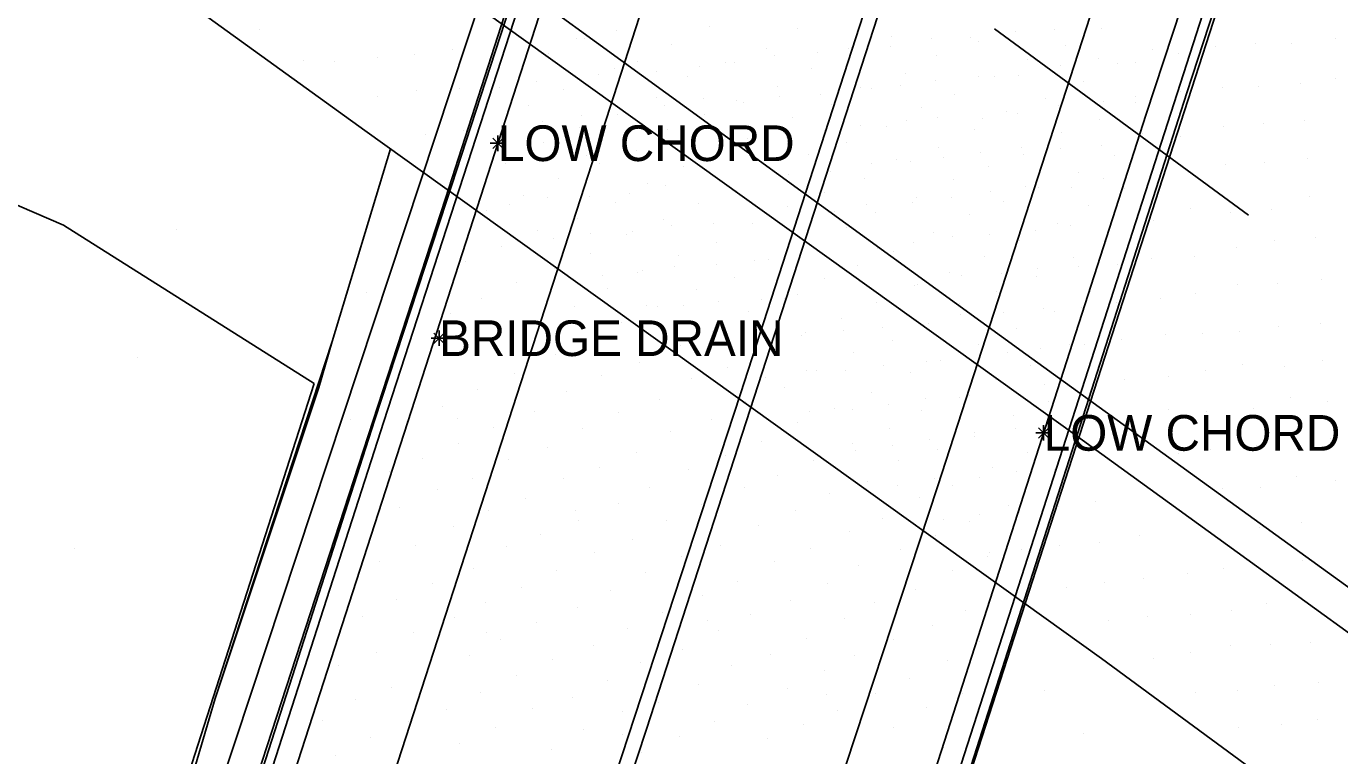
# Model space of a CAD drawing. Extents: x 0 to 1739264, y 0 to 465304.
# Drawn here: x 1738782.8 to 1738849.1, y 464563.4 to 464600.2 of the extents above; entities that cross this region are included whole.
import ezdxf

# ---------------------------------------------------------------- set-up
doc = ezdxf.new("R2010")
doc.units = 0
for name, color, linetype in [('Default', 7, 'Continuous'), ('S_Ground_SpotElevation', 7, 'Continuous'), ('S_Misc_MiscItems', 7, 'Continuous'), ('S_Terrain_Boundary', 7, 'Continuous'), ('S_Terrain_Holes', 7, 'Continuous'), ('S_Terrain_Imported_Contours', 7, 'Continuous'), ('S_Terrain_Low_Points', 7, 'Continuous'), ('S_Terrain_Major_Contours_Label', 7, 'Continuous'), ('S_Terrain_Minor_Contours', 7, 'Continuous'), ('S_Terrain_Spots', 7, 'Continuous'), ('S_Terrain_Triangles', 7, 'Continuous'), ('S_Terrain_Voids', 7, 'Continuous'), ('S_Text', 7, 'Continuous')]:
    doc.layers.add(name, color=color, linetype=linetype)

# ---------------------------------------------------------------- blocks, each defined once
blk = doc.blocks.new('POINT_DISPLAY')
at = {"layer": 'Default'}
blk.add_line((0, 0), (0, 0), dxfattribs=at)

msp = doc.modelspace()

# ---------------------------------------------------------------- linework, layer by layer
at = {"layer": 'S_Misc_MiscItems'}
for p, q in [((1738806.898081, 464594.035019), (1738806.373919, 464594.559181)), ((1738806.898081, 464594.559181), (1738806.373919, 464594.035019)), ((1738806.636, 464594.690025), (1738806.636, 464593.904175)), ((1738807.028925, 464594.2971), (1738806.243075, 464594.2971)), ((1738803.928081, 464584.194319), (1738803.403919, 464584.718481)), ((1738803.928081, 464584.718481), (1738803.403919, 464584.194319)), ((1738803.666, 464584.849325), (1738803.666, 464584.063475)), ((1738804.058925, 464584.4564), (1738803.273075, 464584.4564)), ((1738834.447081, 464579.415419), (1738833.922919, 464579.939581)), ((1738834.447081, 464579.939581), (1738833.922919, 464579.415419)), ((1738834.185, 464580.070425), (1738834.185, 464579.284575)), ((1738834.577925, 464579.6775), (1738833.792075, 464579.6775))]:
    msp.add_line(p, q, dxfattribs=at)
at = {"layer": 'S_Terrain_Boundary'}
msp.add_lwpolyline([(1739175.454702, 464332.756416), (1739132.535909, 464364.041084), (1739089.202901, 464395.459113), (1739026.971303, 464440.302894), (1738965.452398, 464485.286597), (1738903.800699, 464530.134498), (1738862.3172, 464560.363013), (1738835.176198, 464580.019813), (1738796.240903, 464607.926002), (1738740.499395, 464648.201392), (1738691.282796, 464684.125205), (1738636.830999, 464723.670798), (1738593.459401, 464755.033195), (1738538.967885, 464794.669395), (1738484.361104, 464834.444198), (1738424.006185, 464878.237201)], dxfattribs=at)
at = {"layer": 'S_Terrain_Holes'}
msp.add_lwpolyline([(1739170.588308, 464325.500373), (1739152.552907, 464338.483527), (1739114.826696, 464366.236518), (1739080.0463, 464391.153388), (1739045.200704, 464417.071418), (1738978.615499, 464465.012885), (1738944.577802, 464489.97779), (1738904.0454, 464519.108802), (1738859.5087, 464551.815192), (1738837.105501, 464568.288306), (1738799.9269, 464594.941993), (1738767.332898, 464618.452308), (1738734.240804, 464642.564887), (1738701.246496, 464666.335303), (1738672.330098, 464687.406394), (1738626.181707, 464720.896705), (1738547.219503, 464778.355994), (1738497.724386, 464814.494201), (1738418.864705, 464871.408801)], dxfattribs=at)
at = {"layer": 'S_Terrain_Imported_Contours'}
msp.add_line((1738831.709901, 464600.078407), (1738844.528501, 464590.671485), dxfattribs=at)
for points in [[(1738424.884389, 464880.1622), (1738459.014211, 464855.316497), (1738501.687795, 464824.364303), (1738553.815297, 464786.542793), (1738615.385396, 464741.680198), (1738657.550603, 464711.303596), (1738696.071996, 464683.218208), (1738726.299306, 464661.147315), (1738787.670598, 464616.772407), (1738833.2893, 464583.65409), (1738892.3085, 464540.999702), (1738935.664502, 464509.412086), (1738985.514898, 464473.308387), (1739035.486196, 464436.916999), (1739078.275106, 464405.912605), (1739127.816915, 464370.067023), (1739176.551595, 464334.499702)], [(1738861.917132, 464749.554455), (1738852.728099, 464720.865302), (1738834.137899, 464663.640296), (1738810.806299, 464591.494392), (1738798.57878, 464553.775144)], [(1738807.560265, 464547.101191), (1738818.883699, 464581.650611), (1738840.7733, 464649.227912), (1738859.7717, 464707.561698), (1738871.099421, 464743.042961)], [(1738871.2811, 464741.761298), (1738862.9528, 464715.336097), (1738835.861902, 464631.717414), (1738814.1443, 464564.731208), (1738808.177672, 464546.642409)], [(1738816.833754, 464540.526168), (1738828.844899, 464576.996803), (1738841.383399, 464615.664314), (1738851.1298, 464645.487891), (1738867.0642, 464694.79), (1738880.224773, 464736.284008)]]:
    msp.add_lwpolyline(points, dxfattribs=at)
at = {"layer": 'S_Terrain_Low_Points'}
for points in [[(1738792.605864, 464561.753915), (1738808.947702, 464611.187598), (1738829.7665, 464675.843208), (1738844.662601, 464721.815192), (1738854.169417, 464751.567291)], [(1738856.4555, 464747.969505), (1738838.244399, 464692.009101), (1738826.647699, 464655.847602), (1738824.734399, 464649.915199), (1738812.578801, 464612.657905), (1738795.808896, 464560.843085)], [(1738851.7415, 464633.401588), (1738839.363599, 464595.771888), (1738822.210698, 464542.4672)], [(1738801.216888, 464594.017189), (1738798.264997, 464584.296485), (1738792.365444, 464566.267756), (1738791.152246, 464562.167502), (1738792.484382, 464561.299763)]]:
    msp.add_lwpolyline(points, dxfattribs=at)
at = {"layer": 'S_Terrain_Major_Contours_Label'}
for points in [[(1738793.029831, 464557.898451), (1738803.9838, 464591.509406), (1738812.589898, 464618.183295), (1738822.305799, 464648.240607), (1738833.2133, 464681.803199), (1738842.84, 464711.786903), (1738850.196, 464734.470405), (1738856.340829, 464753.508813)], [(1738885.395159, 464732.452095), (1738884.2943, 464729.028999), (1738875.3401, 464701.327995), (1738857.6966, 464646.653999), (1738844.752799, 464606.659614), (1738829.9694, 464560.926002), (1738822.141572, 464536.77828)]]:
    msp.add_lwpolyline(points, dxfattribs=at)
at = {"layer": 'S_Terrain_Minor_Contours'}
for points in [[(1738794.472612, 464560.340831), (1738800.87399, 464580.245445), (1738812.939284, 464617.414493)], [(1738822.502035, 464539.871865), (1738828.574695, 464558.460113), (1738842.68621, 464602.312192), (1738844.286302, 464607.201361)]]:
    msp.add_lwpolyline(points, dxfattribs=at)
at = {"layer": 'S_Terrain_Spots'}
msp.add_lwpolyline([(1738801.216888, 464594.017189), (1738798.264997, 464584.296485), (1738797.595653, 464581.962025), (1738792.365444, 464566.267756), (1738791.152246, 464562.167502)], dxfattribs=at)
at = {"layer": 'S_Terrain_Triangles'}
for points in [[(1738793.143077, 464557.8143), (1738794.925598, 464563.221652), (1738800.413936, 464580.303997), (1738804.057897, 464591.416999), (1738810.426301, 464610.960395), (1738818.2273, 464635.285011), (1738828.789701, 464667.726112), (1738838.3903, 464697.576408), (1738845.034101, 464718.107597), (1738853.3717, 464743.659003), (1738856.448989, 464753.432112)], [(1738885.339743, 464732.493165), (1738884.4636, 464729.823402), (1738878.6737, 464712.005698), (1738871.4064, 464689.647605), (1738862.8085, 464662.946113), (1738850.8758, 464625.801398), (1738841.409499, 464596.833595), (1738830.533101, 464562.882606), (1738822.877599, 464539.516792), (1738822.019587, 464536.864414)]]:
    msp.add_lwpolyline(points, dxfattribs=at)
at = {"layer": 'S_Terrain_Voids'}
msp.add_line((1738797.357, 464582.164802), (1738791.034597, 464562.502906), dxfattribs=at)
msp.add_lwpolyline([(1738657.937398, 464655.498206), (1738707.784398, 464616.152808), (1738731.372304, 464597.946906), (1738739.378301, 464595.018104), (1738746.050298, 464593.852699), (1738752.398702, 464595.526496), (1738762.3794, 464598.047309), (1738774.3215, 464594.638404), (1738784.707403, 464590.162605), (1738797.357, 464582.164802)], dxfattribs=at)

# ---------------------------------------------------------------- block references
at = {"layer": 'S_Ground_SpotElevation'}
for p in [(1738794.62611, 464600.041525), (1738812.635814, 464599.998922), (1738817.322993, 464600.199699), (1738821.761897, 464600.074516), (1738832.786998, 464599.9186), (1738834.735302, 464600.02532), (1738837.115001, 464600.077324), (1738806.440105, 464599.136526), (1738810.58131, 464599.601827), (1738810.998393, 464599.600273), (1738815.380595, 464599.280205), (1738820.198695, 464599.074089), (1738824.336192, 464599.061516), (1738824.484997, 464599.108816), (1738826.475902, 464599.183004), (1738826.493693, 464599.671989), (1738828.547405, 464599.584219), (1738830.494793, 464599.64562), (1738830.9136, 464599.447197), (1738835.266902, 464599.214226), (1738842.864299, 464599.174703), (1738844.886608, 464599.310812), (1738846.697796, 464599.342703), (1738848.933086, 464599.566305), (1738796.803905, 464598.474508), (1738798.397014, 464598.413625), (1738800.560894, 464598.612722), (1738802.420696, 464598.768118), (1738804.348095, 464599.043111), (1738809.175395, 464598.821403), (1738813.692195, 464598.410515), (1738820.601391, 464598.713705), (1738822.745891, 464598.865621), (1738828.783198, 464598.733391), (1738833.389293, 464598.545219), (1738836.936504, 464598.5548), (1738839.676799, 464599.014274), (1738840.975689, 464598.83251), (1738811.732799, 464597.782524), (1738812.529888, 464598.048116), (1738814.664196, 464597.928518), (1738816.797893, 464598.162222), (1738818.115703, 464598.362602), (1738818.586712, 464598.348806), (1738822.4743, 464598.056023), (1738827.226298, 464597.82), (1738835.035503, 464598.206411), (1738837.932704, 464598.306328), (1738838.822704, 464598.353506), (1738806.694408, 464597.122823), (1738808.585094, 464597.398611), (1738816.194804, 464597.654289), (1738820.760493, 464597.137993), (1738824.945812, 464597.127218), (1738825.482494, 464597.069816), (1738826.9622, 464597.220113), (1738828.733989, 464597.48171), (1738830.895611, 464597.642721), (1738831.711696, 464597.652519), (1738832.892009, 464597.728323), (1738836.188899, 464597.413017), (1738843.191997, 464597.087301), (1738845.041485, 464597.135915), (1738847.146892, 464597.300314), (1738848.895885, 464597.584402), (1738800.567211, 464596.648519), (1738802.536297, 464596.948812), (1738804.700512, 464597.068014), (1738809.932994, 464596.998405), (1738814.644298, 464596.594108), (1738817.011913, 464596.544424), (1738818.670299, 464596.461202), (1738820.860698, 464596.638021), (1738822.900707, 464596.735403), (1738829.6804, 464596.738029), (1738834.277995, 464596.557487), (1738837.181987, 464596.424612), (1738838.829998, 464596.662405), (1738841.081585, 464596.906118), (1738808.175105, 464596.176872), (1738815.045299, 464596.190725), (1738817.061595, 464595.751884), (1738819.043193, 464596.329704), (1738823.459407, 464596.246025), (1738828.0312, 464596.11663), (1738832.294398, 464595.922172), (1738832.882915, 464595.798513), (1738834.956615, 464596.208212), (1738838.840495, 464596.348076), (1738807.049297, 464595.156026), (1738808.897289, 464595.407217), (1738810.851207, 464595.713216), (1738812.681407, 464595.732719), (1738821.509196, 464595.618828), (1738824.933788, 464595.202505), (1738826.245296, 464595.165581), (1738827.274212, 464595.448019), (1738828.825908, 464595.603811), (1738831.119915, 464595.549429), (1738836.986995, 464595.516716), (1738843.260296, 464595.141103), (1738845.274608, 464595.269827), (1738847.334697, 464595.420705), (1738802.972088, 464594.751302), (1738804.8903, 464594.945699), (1738810.771403, 464595.077019), (1738815.185695, 464594.9804), (1738819.260296, 464594.53832), (1738819.614299, 464594.644401), (1738821.199596, 464594.577322), (1738823.123485, 464594.925222), (1738830.689006, 464594.982292), (1738835.096095, 464594.834892), (1738839.161602, 464594.809011), (1738841.090801, 464594.657217), (1738808.945293, 464594.33007), (1738812.964489, 464593.928701), (1738813.611095, 464593.934929), (1738817.908595, 464593.7976), (1738824.249095, 464594.32061), (1738828.868907, 464594.101311), (1738831.003002, 464593.848409), (1738833.073405, 464594.063896), (1738835.027385, 464594.037801), (1738837.120586, 464594.160024), (1738807.0247, 464593.278921), (1738807.233501, 464593.434807), (1738809.14381, 464593.376424), (1738811.114513, 464593.678426), (1738811.763698, 464593.266289), (1738816.009196, 464593.111809), (1738822.338405, 464593.718986), (1738825.487102, 464593.257711), (1738826.745296, 464593.458427), (1738827.485393, 464593.378103), (1738829.148693, 464593.551901), (1738831.4062, 464593.098198), (1738833.176586, 464593.735799), (1738837.761806, 464593.684807), (1738843.373394, 464593.2152), (1738845.353985, 464593.334921), (1738847.509105, 464593.535604), (1738805.058788, 464592.985799), (1738809.712703, 464592.502006), (1738820.482097, 464592.976616), (1738821.285808, 464592.725729), (1738823.430706, 464592.874899), (1738825.149699, 464592.505607), (1738829.628596, 464592.474419), (1738835.9304, 464592.833305), (1738837.2057, 464592.5324), (1738839.6432, 464592.562124), (1738841.481701, 464592.858907), (1738813.255413, 464591.780019), (1738814.206401, 464592.281608), (1738815.083996, 464592.152609), (1738818.685695, 464591.898125), (1738823.120204, 464591.827019), (1738831.493389, 464591.86321), (1738833.268291, 464592.126302), (1738833.904399, 464592.084587), (1738835.585308, 464592.077505), (1738838.275401, 464591.987724), (1738807.231212, 464591.215414), (1738807.9239, 464591.670402), (1738809.1226, 464591.550222), (1738811.265514, 464591.592123), (1738812.593394, 464591.329399), (1738816.784694, 464591.257378), (1738821.279903, 464591.112297), (1738825.248211, 464591.222616), (1738827.546001, 464591.316), (1738827.760005, 464591.563408), (1738829.556102, 464591.532827), (1738832.150996, 464591.333), (1738836.463695, 464591.153007), (1738847.6161, 464591.631307), (1738806.068996, 464590.923271), (1738810.632503, 464590.493828), (1738815.013805, 464590.45507), (1738823.628887, 464590.833517), (1738825.720195, 464590.822014), (1738830.434306, 464590.716301), (1738837.647899, 464590.538808), (1738841.61549, 464590.989523), (1738843.601085, 464590.800619), (1738845.674602, 464590.973409), (1738790.424195, 464589.926617), (1738808.642604, 464589.8778), (1738813.419109, 464589.827627), (1738815.415111, 464590.150228), (1738817.500103, 464590.234914), (1738819.507198, 464590.243889), (1738824.241099, 464590.022087), (1738828.647395, 464589.777031), (1738833.779888, 464589.890829), (1738834.874004, 464590.228996), (1738835.552898, 464590.130026), (1738839.717601, 464590.381826), (1738809.461803, 464589.482015), (1738811.323101, 464589.737814), (1738813.147594, 464589.70208), (1738817.653194, 464589.271721), (1738822.163905, 464589.355888), (1738827.630687, 464589.2759), (1738829.564892, 464589.605001), (1738831.42921, 464589.695303), (1738832.942607, 464589.393303), (1738837.379207, 464589.34948), (1738845.859813, 464589.3897), (1738847.885692, 464589.528219), (1738806.810603, 464589.100517), (1738811.297298, 464588.723503), (1738815.774104, 464588.625297), (1738825.791698, 464588.985128), (1738826.581493, 464588.857292), (1738831.208903, 464588.580803), (1738835.674495, 464588.544914), (1738839.635692, 464588.4634), (1738841.802105, 464588.604513), (1738843.912609, 464589.032308), (1738804.997203, 464588.34301), (1738809.479793, 464587.953483), (1738813.957896, 464587.878899), (1738815.5471, 464588.055929), (1738817.674907, 464588.159322), (1738819.611187, 464588.402822), (1738820.286296, 464588.426506), (1738824.771999, 464588.101494), (1738829.430598, 464587.791984), (1738833.886791, 464587.987203), (1738835.952587, 464588.051015), (1738837.924205, 464588.194601), (1738807.598003, 464587.246879), (1738811.909588, 464587.622823), (1738813.661998, 464587.777425), (1738818.581401, 464587.532585), (1738823.143397, 464587.457207), (1738827.649898, 464587.125603), (1738827.802013, 464587.180929), (1738830.022686, 464587.601308), (1738832.06541, 464587.708303), (1738833.847896, 464587.581291), (1738843.979595, 464587.143819), (1738846.003307, 464587.234914), (1738848.200206, 464587.420126), (1738800.012605, 464586.781414), (1738805.809795, 464586.461479), (1738812.190303, 464586.973686), (1738816.648296, 464586.910271), (1738821.7765, 464586.682699), (1738831.812297, 464586.832695), (1738836.528499, 464586.800224), (1738841.843212, 464586.719503), (1738810.512294, 464586.061577), (1738814.145702, 464586.104116), (1738814.716899, 464586.048088), (1738815.987102, 464586.084127), (1738817.758312, 464586.303304), (1738819.281398, 464585.801201), (1738819.930309, 464586.422903), (1738821.117793, 464586.458427), (1738825.766902, 464586.241508), (1738829.945003, 464586.192985), (1738834.160595, 464585.934011), (1738836.103496, 464586.005819), (1738837.879192, 464586.274007), (1738840.088787, 464586.458425), (1738804.223308, 464585.695427), (1738808.490398, 464585.275383), (1738812.894496, 464585.228325), (1738823.974605, 464585.458916), (1738828.392696, 464585.202629), (1738829.987011, 464585.658102), (1738832.133098, 464585.729726), (1738834.739802, 464585.789909), (1738848.135296, 464585.188314), (1738806.726207, 464584.472893), (1738817.462794, 464584.773613), (1738820.047497, 464584.575216), (1738821.979809, 464584.593801), (1738822.179805, 464584.75872), (1738824.102611, 464584.831411), (1738826.041088, 464584.996725), (1738832.798793, 464584.937309), (1738840.315105, 464584.641103), (1738842.214794, 464584.681203), (1738844.078991, 464584.806417), (1738846.02351, 464585.044607), (1738804.783107, 464583.874077), (1738811.1067, 464584.347771), (1738815.829402, 464584.066704), (1738817.971386, 464584.223318), (1738820.327403, 464583.900993), (1738826.537395, 464584.332573), (1738830.892894, 464584.117973), (1738834.021801, 464583.960226), (1738835.472301, 464584.159721), (1738836.237194, 464584.153616), (1738838.136089, 464584.399221), (1738788.420792, 464583.502117), (1738809.549403, 464583.626579), (1738813.807201, 464583.245293), (1738824.608607, 464583.75219), (1738828.24699, 464583.283529), (1738828.9985, 464583.339592), (1738832.361004, 464583.751913), (1738848.276714, 464583.35201), (1738802.954204, 464583.00988), (1738807.451305, 464582.663383), (1738811.850093, 464582.587517), (1738818.227504, 464582.956291), (1738822.23109, 464582.812612), (1738822.740199, 464582.815422), (1738824.163799, 464582.842519), (1738826.10429, 464583.087301), (1738827.454906, 464582.721794), (1738833.535503, 464583.066215), (1738840.486614, 464582.510702), (1738842.37379, 464582.818014), (1738844.212993, 464583.115621), (1738846.327587, 464583.033407), (1738805.623698, 464581.865227), (1738816.401393, 464582.402092), (1738820.152294, 464582.453909), (1738821.107997, 464581.984001), (1738831.732204, 464582.376274), (1738834.2346, 464582.141927), (1738836.645794, 464582.143423), (1738838.244487, 464582.359914), (1738810.074992, 464581.746208), (1738814.811198, 464581.381828), (1738819.114207, 464581.243584), (1738825.512004, 464581.697502), (1738828.232891, 464581.405325), (1738829.945995, 464581.481071), (1738830.434093, 464581.558401), (1738834.4519, 464581.254204), (1738846.641796, 464581.482504), (1738848.507, 464581.237905), (1738803.853206, 464580.997917), (1738808.469707, 464580.774284), (1738812.700404, 464580.696831), (1738822.350689, 464580.732717), (1738823.619502, 464580.914116), (1738824.539715, 464580.858602), (1738826.345806, 464581.119802), (1738828.039104, 464580.793693), (1738832.665507, 464580.545402), (1738840.499889, 464580.874319), (1738842.396709, 464580.751913), (1738844.755809, 464580.891317), (1738799.216706, 464580.341961), (1738802.027995, 464580.272514), (1738804.604398, 464580.397985), (1738806.429393, 464579.967583), (1738810.894298, 464579.892876), (1738817.395, 464580.33593), (1738821.734996, 464580.219719), (1738826.387996, 464579.905571), (1738832.777385, 464579.876516), (1738836.789501, 464580.274007), (1738838.637493, 464580.211202), (1738815.339503, 464579.756401), (1738819.931102, 464579.265373), (1738828.442913, 464579.348501), (1738830.686809, 464579.5035), (1738830.691005, 464579.678215), (1738848.678386, 464579.3897), (1738804.629802, 464579.152397), (1738809.153697, 464578.962028), (1738813.6076, 464578.686027), (1738818.137401, 464578.523918), (1738824.557994, 464579.152519), (1738824.697307, 464578.808614), (1738826.531994, 464579.055624), (1738828.831996, 464578.844475), (1738833.369395, 464578.693718), (1738840.974895, 464578.617513), (1738842.607311, 464578.814108), (1738844.950298, 464579.063924), (1738846.9463, 464579.149923), (1738802.837703, 464578.391716), (1738807.194301, 464578.345817), (1738811.783702, 464577.940422), (1738822.579799, 464578.290703), (1738826.868205, 464578.288872), (1738831.605495, 464577.937614), (1738834.7234, 464577.844228), (1738801.178798, 464577.736198), (1738805.369701, 464577.356193), (1738809.938792, 464577.378593), (1738816.250499, 464577.814873), (1738820.750499, 464577.51403), (1738825.294597, 464577.233086), (1738828.669597, 464577.3561), (1738830.928692, 464577.435903), (1738832.836986, 464577.724599), (1738846.931591, 464577.468008), (1738848.897899, 464577.294302), (1738803.592006, 464576.832512), (1738814.304195, 464576.907829), (1738819.095805, 464576.911919), (1738823.392802, 464576.597282), (1738826.809307, 464577.019125), (1738829.5993, 464577.040214), (1738843.223186, 464576.850423), (1738845.122692, 464576.937917), (1738801.686702, 464575.899773), (1738808.022395, 464576.372795), (1738812.738505, 464576.128288), (1738816.938304, 464576.080315), (1738827.903804, 464576.418815), (1738832.395305, 464575.992302), (1738834.946209, 464575.947408), (1738836.80299, 464576.222921), (1738806.150905, 464575.740471), (1738810.536, 464575.772405), (1738810.729396, 464575.26403), (1738815.145305, 464575.278007), (1738821.677302, 464575.749077), (1738826.048503, 464575.377495), (1738829.126812, 464575.321005), (1738830.456798, 464575.194023), (1738830.954998, 464575.573019), (1738832.971386, 464575.638326), (1738804.387904, 464574.969108), (1738808.782298, 464574.564384), (1738819.810298, 464575.014091), (1738824.373393, 464574.682182), (1738845.089397, 464574.878622), (1738847.225811, 464575.152609), (1738785.243302, 464573.866375), (1738800.0631, 464574.085302), (1738802.500697, 464573.988579), (1738807.073497, 464573.965996), (1738813.452693, 464574.293388), (1738817.888194, 464573.992912), (1738828.717403, 464574.481315), (1738835.004009, 464574.009512), (1738837.029308, 464574.157217), (1738839.003185, 464574.476705), (1738811.521098, 464573.621696), (1738815.898296, 464573.441276), (1738822.418605, 464573.855827), (1738826.943004, 464573.77343), (1738831.355098, 464573.425774), (1738831.470806, 464573.647726), (1738833.070507, 464573.798421), (1738847.236889, 464573.223714), (1738800.657603, 464573.187004), (1738805.400996, 464572.84832), (1738809.600398, 464572.731499), (1738814.066707, 464572.61071), (1738820.580104, 464573.172905), (1738824.863704, 464573.006523), (1738829.594005, 464572.726982), (1738841.423198, 464572.565603), (1738843.256786, 464572.829214), (1738803.343196, 464572.05999), (1738807.831706, 464571.894585), (1738818.747096, 464572.197685), (1738823.291103, 464572.056328), (1738833.49699, 464572.12911), (1738835.345012, 464571.885824), (1738837.260509, 464572.100607), (1738839.24461, 464572.312521), (1738801.506007, 464571.291984), (1738812.316997, 464571.698723), (1738816.972896, 464571.465019), (1738821.420299, 464571.214897), (1738827.7261, 464571.781914), (1738795.710099, 464571.074688), (1738806.003902, 464571.140373), (1738810.644496, 464570.860527), (1738814.961192, 464570.602775), (1738825.633098, 464571.126274), (1738830.218303, 464570.732231), (1738843.668895, 464570.689504), (1738845.421795, 464571.072713), (1738799.777003, 464570.418205), (1738804.428096, 464570.379204), (1738808.5834, 464570.123894), (1738817.218198, 464570.224096), (1738819.369502, 464570.486992), (1738824.119807, 464570.304924), (1738828.566905, 464569.980278), (1738837.480114, 464570.210928), (1738839.411998, 464570.412618), (1738841.619396, 464570.493124), (1738802.377895, 464569.601128), (1738806.067101, 464569.620702), (1738806.778407, 464569.259514), (1738813.165004, 464569.800102), (1738817.794795, 464569.689384), (1738822.208202, 464569.32), (1738826.626002, 464569.241814), (1738800.525203, 464568.605217), (1738811.439403, 464568.965019), (1738815.932307, 464568.753593), (1738830.930507, 464569.145073), (1738841.622692, 464568.600423), (1738843.630687, 464568.947622), (1738845.644695, 464568.997427), (1738847.6739, 464569.077505), (1738798.595607, 464567.912529), (1738805.216304, 464568.449089), (1738809.385402, 464568.250603), (1738813.820201, 464568.093925), (1738818.417003, 464567.938774), (1738820.395396, 464568.51403), (1738824.638805, 464568.443107), (1738829.322703, 464568.193596), (1738839.746105, 464568.269613), (1738803.109996, 464567.792412), (1738807.592296, 464567.408501), (1738823.119304, 464567.695122), (1738827.414104, 464567.298271), (1738801.255702, 464566.822807), (1738805.733501, 464566.595695), (1738812.163203, 464567.199211), (1738816.755901, 464566.987114), (1738821.264796, 464566.783684), (1738834.2104, 464566.659887), (1738843.990093, 464566.671926), (1738845.839306, 464566.931814), (1738848.075512, 464567.103017), (1738799.433101, 464566.227898), (1738810.4239, 464566.340019), (1738814.742, 464566.093925), (1738819.214, 464565.987419), (1738823.248101, 464566.46311), (1738825.721706, 464566.506401), (1738830.106898, 464566.527214), (1738841.8596, 464566.564718), (1738804.057506, 464565.72747), (1738808.382503, 464565.785576), (1738812.924693, 464565.637993), (1738823.781993, 464565.672722), (1738828.248897, 464565.804375), (1738797.771602, 464565.173698), (1738802.143397, 464565.108024), (1738806.533198, 464564.783195), (1738810.967998, 464564.71331), (1738817.553203, 464565.086174), (1738822.070796, 464564.966728), (1738826.586299, 464564.782585), (1738844.038494, 464564.820211), (1738846.167186, 464564.937307), (1738848.008312, 464565.195119), (1738800.225001, 464564.318718), (1738804.690196, 464564.006706), (1738812.921498, 464564.438299), (1738815.802302, 464564.366875), (1738820.269893, 464564.2752), (1738836.183305, 464564.48222), (1738798.4463, 464563.393181), (1738809.365199, 464563.674919), (1738813.908198, 464563.561699), (1738824.471797, 464563.840874), (1738829.1524, 464563.809379)]:
    msp.add_blockref('POINT_DISPLAY', p, dxfattribs=at)

# ---------------------------------------------------------------- texts
at = {"layer": 'S_Text'}
for s, p in [('LOW CHORD', (1738806.636, 464593.3971)), ('BRIDGE DRAIN', (1738803.666, 464583.5564)), ('LOW CHORD', (1738834.185, 464578.7775))]:
    msp.add_text(s, height=1.8, dxfattribs=at).set_placement(p)

doc.saveas('drawing.dxf')
